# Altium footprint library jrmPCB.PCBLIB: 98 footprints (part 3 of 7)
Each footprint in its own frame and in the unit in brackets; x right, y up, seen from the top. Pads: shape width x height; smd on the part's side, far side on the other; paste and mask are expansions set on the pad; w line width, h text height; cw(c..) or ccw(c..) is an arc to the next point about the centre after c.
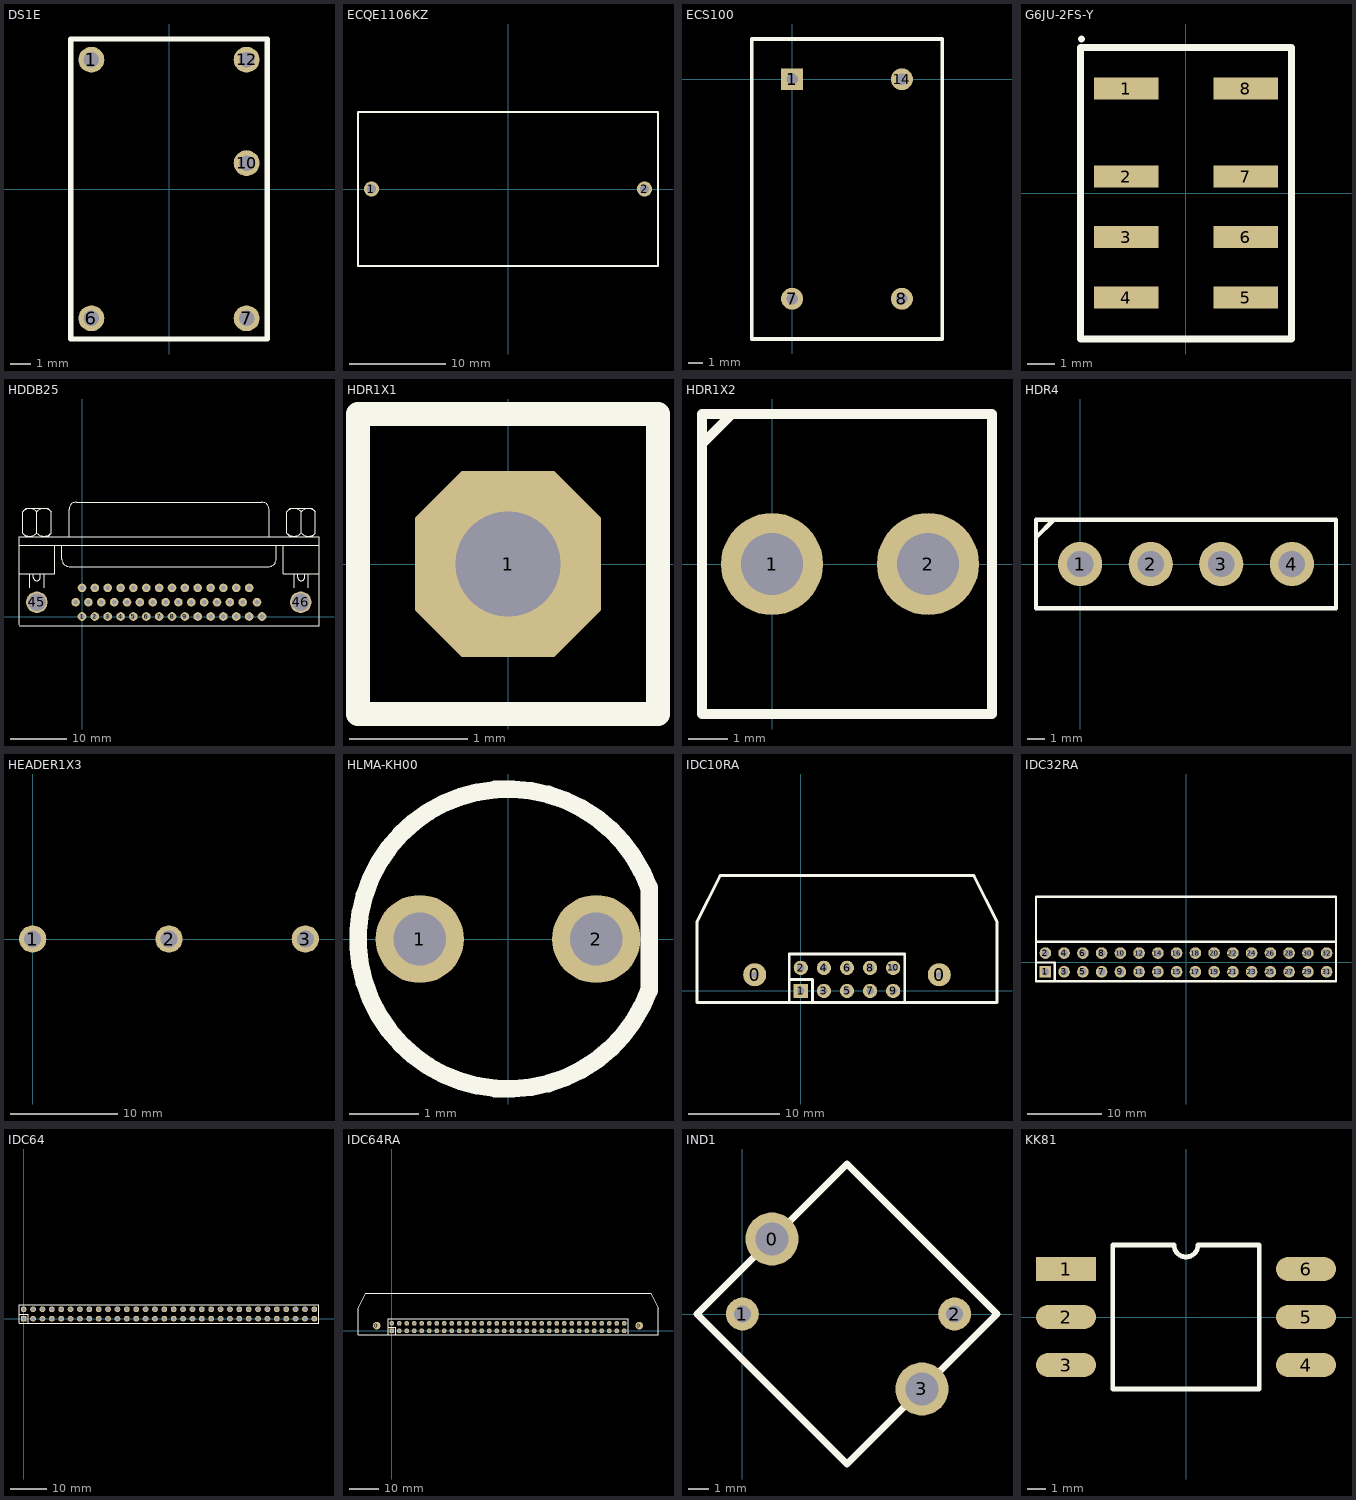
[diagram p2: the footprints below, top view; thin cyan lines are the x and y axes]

## DS1E [mil]
pads (5):
  round 50 hole 30: 1(-150,250) 6(-150,-250) 7(150,-250) 10(150,50) 12(150,250)
Top Overlay:
  lines w10: -190,-290 -190,290 190,290 190,-290 -190,-290

## ECQE1106KZ [mil]
pads (2):
  round 62 hole 35: 1(-557.09,0) 2(557.09,0)
Top Overlay:
  lines w7.87: -612.05,-314.96 -557.09,-314.96 557.09,-314.96 612.05,-314.96 612.05,314.96 557.09,314.96 -557.09,314.96 -612.05,314.96 -612.05,-314.96

## ECS100 [mil]
pads (4):
  rect 60x60 hole 32: 1(0,0)
  round 60 hole 32: 7(0,-600) 8(300,-600) 14(300,0)
Top Overlay:
  lines w10: -110,-710 410,-710 410,110 -110,110 -110,-710

## G6JU-2FS-Y [mm] "RELAY LATCH DPDT 1A 5VDC SMD"
pads (8):
  rect 2.35x0.8 smd: 1(-2.175,3.8) 2(-2.175,0.6) 3(-2.175,-1.6) 4(-2.175,-3.8) 5(2.175,-3.8) 6(2.175,-1.6) 7(2.175,0.6) 8(2.175,3.8)
Top Overlay:
  circle w0.254: c-3.8,5.6 r0
  lines w0.254: -3.825,-5.3 3.825,-5.3 3.825,5.3 -3.825,5.3 -3.825,-5.3

## HDDB25 [mil]
pads (46):
  round 60 hole 32: 1(0,0) 2(90,0) 3(180,0) 4(270,0) 5(360,0) 6(450,0) 7(540,0) 8(630,0) 9(720,0) 10(810,0) 11(900,0) 12(990,0) 13(1080,0) 14(1170,0) 15(1260,0) 16(-45,100) 17(45,100) 18(135,100) 19(225,100) 20(315,100) 21(405,100) 22(495,100) 23(585,100) 24(675,100) 25(765,100) 26(855,100) 27(945,100) 28(1035,100) 29(1125,100) 30(1225,100) 31(0,200) 32(90,200) 33(180,200) 34(270,200) 35(360,200) 36(450,200) 37(540,200) 38(630,200) 39(720,200) 40(810,200) 41(900,200) 42(990,200) 43(1080,200) 44(1170,200)
  round 150 hole 125: 45(-316,100) 46(1531,100)
Top Overlay:
  lines w8: -441,-65 1659,-65 1659,558.33 -441,558.33 -441,-56.67 ; -441,300 -191,300 -191,500 ; -441,500 1659,500 ; -416.09,583.25 ccw(c-366,633.33) -315.91,583.25 ; -416.09,733.42 cw(c-366,683.33) -315.91,733.42 ; -391,558.33 -416,583.33 -416,733.33 -391,758.33 -241,758.33 -216,733.33 -216,583.33 -241,558.33 ; -366,200 -366,300 ; -341,300 -341,275 ccw(c-316,275) -291,275 -291,300 ; -316.09,583.25 ccw(c-266,633.33) -215.91,583.25 ; -316.09,733.42 cw(c-266,683.33) -215.91,733.42 ; -316,583.33 -316,733.33 ; -266,200 -266,300 ; -141,500 -141,400 ccw(c-91,400) -91,350 1309,350 ccw(c1309,400) 1359,400 1359,500 ; -91,558.33 -91,750 cw(c-41,750) -41,800 1234,800 1259,800 cw(c1259,750) 1309,750 1309,558.33 ; 1409,500 1409,300 1659,300 ; 1433.91,583.25 ccw(c1484,633.33) 1534.09,583.25 ; 1433.91,733.42 cw(c1484,683.33) 1534.09,733.42 ; 1459,558.33 1434,583.33 1434,733.33 1459,758.33 1609,758.33 1634,733.33 1634,583.33 1609,558.33 ; 1484,200 1484,300 ; 1509,300 1509,275 ccw(c1534,275) 1559,275 1559,300 ; 1533.91,583.25 ccw(c1584,633.33) 1634.09,583.25 ; 1533.91,733.42 cw(c1584,683.33) 1634.09,733.42 ; 1534,583.33 1534,733.33 ; 1584,200 1584,300

## HDR1X1 [mil]
pads (1):
  oct 62x62 hole 35: 1(0,0)
Top Overlay:
  lines w8: -50,-50 50,-50 50,50 -50,50 -50,-50

## HDR1X2 [mil]
pads (2):
  round 102 hole 62: 1(0,0) 2(156,0)
Top Overlay:
  lines w10: -70,120 -40,150 ; -70,-150 0,-150 150,-150 220,-150 220,150 150,150 0,150 -70,150 -70,-150

## HDR4 [mil]
pads (4):
  round 100 hole 60: 1(0,0) 2(160,0) 3(320,0) 4(480,0)
Top Overlay:
  lines w10: -100,60 -60,100 ; -100,-100 580,-100 580,100 -100,100 -100,-100

## HEADER1X3 [mil]
pads (3):
  round 100 hole 63: 1(0,0) 2(500,0) 3(1000,0)

## HLMA-KH00 [mil]
pads (2):
  round 50 hole 30: 1(-50,0) 2(50,0)
Top Overlay:
  lines w10: 79.87,-29.07 cw(c0,0) 79.87,29.07 ; 80,-29.14 80,29.14

## IDC10RA [mil]
pads (12):
  round 100 hole 28: 0(-200,70) 0(600,70)
  rect 62x62 hole 32: 1(0,0)
  round 62 hole 32: 2(0,100) 3(100,0) 4(100,100) 5(200,0) 6(200,100) 7(300,0) 8(300,100) 9(400,0) 10(400,100)
Top Overlay:
  lines w12: -50,-50 -50,50 50,50 50,-50 ; -50,-40 -50,160 450,160 450,-40 ; -450,-50 -450,300 -350,500 750,500 850,300 850,-50 -450,-50

## IDC32RA [mil] "Right angle IDC header"
pads (32):
  rect 62x62 hole 40: 1(-750,-50)
  round 62 hole 40: 2(-750,50) 3(-650,-50) 4(-650,50) 5(-550,-50) 6(-550,50) 7(-450,-50) 8(-450,50) 9(-350,-50) 10(-350,50) 11(-250,-50) 12(-250,50) 13(-150,-50) 14(-150,50) 15(-50,-50) 16(-50,50) 17(50,-50) 18(50,50) 19(150,-50) 20(150,50) 21(250,-50) 22(250,50) 23(350,-50) 24(350,50) 25(450,-50) 26(450,50) 27(550,-50) 28(550,50) 29(650,-50) 30(650,50) 31(750,-50) 32(750,50)
Top Layer:
  lines w10: 790,110 800,110
Top Overlay:
  lines w10: 800,-100 800,110
  lines w12: -800,-90 -800,110 ; -700,-100 -700,0 -800,0 -800,-100 800,-100 ; -800,110 -800,350 800,350 800,110 -800,110

## IDC64 [mil]
pads (64):
  rect 62x62 hole 40: 1(0,0)
  round 62 hole 40: 2(0,100) 3(100,0) 4(100,100) 5(200,0) 6(200,100) 7(300,0) 8(300,100) 9(400,0) 10(400,100) 11(500,0) 12(500,100) 13(600,0) 14(600,100) 15(700,0) 16(700,100) 17(800,0) 18(800,100) 19(900,0) 20(900,100) 21(1000,0) 22(1000,100) 23(1100,0) 24(1100,100) 25(1200,0) 26(1200,100) 27(1300,0) 28(1300,100) 29(1400,0) 30(1400,100) 31(1500,0) 32(1500,100) 33(1600,0) 34(1600,100) 35(1700,0) 36(1700,100) 37(1800,0) 38(1800,100) 39(1900,0) 40(1900,100) 41(2000,0) 42(2000,100) 43(2100,0) 44(2100,100) 45(2200,0) 46(2200,100) 47(2300,0) 48(2300,100) 49(2400,0) 50(2400,100) 51(2500,0) 52(2500,100) 53(2600,0) 54(2600,100) 55(2700,0) 56(2700,100) 57(2800,0) 58(2800,100) 59(2900,0) 60(2900,100) 61(3000,0) 62(3000,100) 63(3100,0) 64(3100,100)
Top Overlay:
  lines w12: -50,50 50,50 50,-50 ; -50,-50 3150,-50 3150,150 -50,150 -50,-50

## IDC64RA [mil]
pads (66):
  round 100 hole 28: 0(-200,70) 0(3300,70)
  rect 62x62 hole 32: 1(0,0)
  round 62 hole 32: 2(0,100) 3(100,0) 4(100,100) 5(200,0) 6(200,100) 7(300,0) 8(300,100) 9(400,0) 10(400,100) 11(500,0) 12(500,100) 13(600,0) 14(600,100) 15(700,0) 16(700,100) 17(800,0) 18(800,100) 19(900,0) 20(900,100) 21(1000,0) 22(1000,100) 23(1100,0) 24(1100,100) 25(1200,0) 26(1200,100) 27(1300,0) 28(1300,100) 29(1400,0) 30(1400,100) 31(1500,0) 32(1500,100) 33(1600,0) 34(1600,100) 35(1700,0) 36(1700,100) 37(1800,0) 38(1800,100) 39(1900,0) 40(1900,100) 41(2000,0) 42(2000,100) 43(2100,0) 44(2100,100) 45(2200,0) 46(2200,100) 47(2300,0) 48(2300,100) 49(2400,0) 50(2400,100) 51(2500,0) 52(2500,100) 53(2600,0) 54(2600,100) 55(2700,0) 56(2700,100) 57(2800,0) 58(2800,100) 59(2900,0) 60(2900,100) 61(3000,0) 62(3000,100) 63(3100,0) 64(3100,100)
Top Overlay:
  lines w12: -50,-50 -50,50 50,50 50,-50 ; -50,-40 -50,160 3150,160 3150,-40 ; -450,-50 3550,-50 3550,300 3450,500 -350,500 -450,300 -450,-50

## IND1 [mil]
pads (4):
  round 100 hole 62: 0(55.74,141.42) 3(338.58,-141.42)
  round 62 hole 32: 1(0,0) 2(400,0)
Top Overlay:
  lines w14: -85.69,0 197.16,282.84 480,0 197.16,-282.84 -85.69,0

## KK81 [mil]
pads (6):
  rect 125x50 smd: 1(-250,100)
  oval 125x50 smd: 2(-250,0) 3(-250,-100) 4(250,-100) 5(250,0) 6(250,100)
Top Overlay:
  lines w10: -152.5,-150 -152.5,150 ; -150,-150 150,-150 ; -150,150 -25,150 ccw(c0,150) 25,150 150,150 ; 152.5,-150 152.5,150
